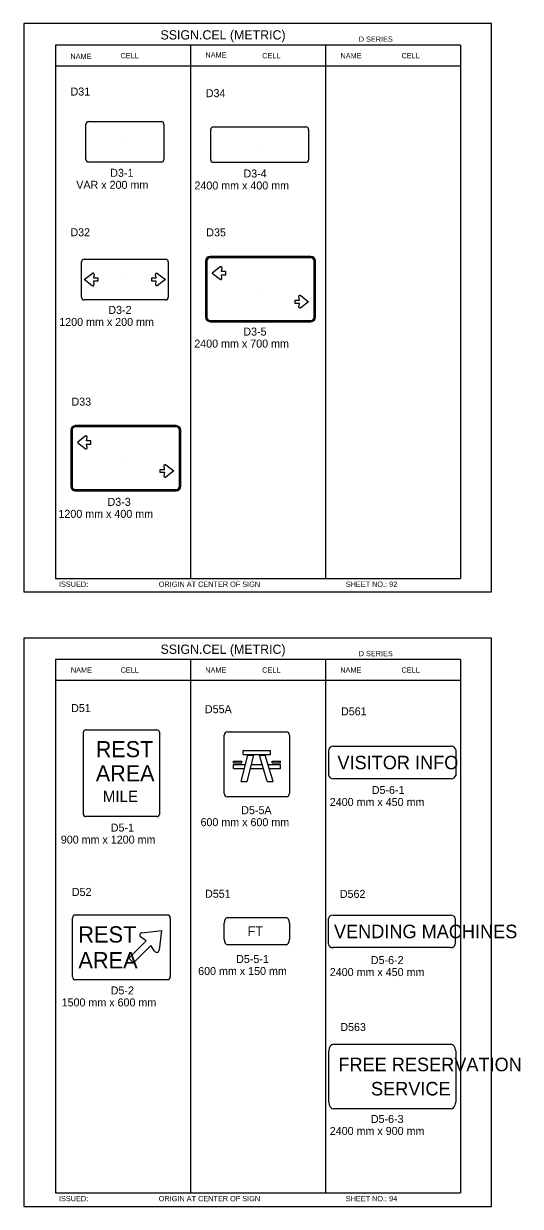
# Model space of a CAD drawing. Extents: x -12 to 6962, y -3756 to 679.
# Drawn here: x 4391.6 to 4577.7, y -235.4 to 208 of the extents above; entities that cross this region are included whole.
import ezdxf

# ---------------------------------------------------------------- set-up
doc = ezdxf.new("R2010")
doc.units = 0
for name, color, linetype in [('Level 1', 7, 'Continuous'), ('Level 2', 7, 'Continuous'), ('Level 3', 7, 'Continuous'), ('Level 61', 7, 'Continuous')]:
    doc.layers.add(name, color=color, linetype=linetype)

msp = doc.modelspace()

# ---------------------------------------------------------------- linework, layer by layer
at = {"layer": 'Level 1'}
for p, q in [((4555.25, 200), (4403.5, 200)), ((4403.5, 200), (4403.5, 0)), ((4454.08, 200), (4454.08, 0)), ((4504.67, 200), (4504.67, 0)), ((4555.25, 200), (4555.25, 0)), ((4555.25, 192.08), (4403.5, 192.08)), ((4414.93, 157.11), (4414.93, 170.35)), ((4415.93, 171.35), (4443.11, 171.35)), ((4444.11, 170.35), (4444.11, 157.11)), ((4462.7, 169.33), (4497.33, 169.33)), ((4461.7, 157), (4461.7, 168.33)), ((4498.33, 168.33), (4498.33, 157)), ((4429.52, 163.73), (4429.52, 163.73)), ((4480.02, 162.66), (4480.02, 162.66)), ((4443.11, 156.11), (4415.93, 156.11)), ((4497.33, 156), (4462.7, 156)), ((4499.24, 120.78), (4461.43, 120.78)), ((4499.24, 120.28), (4461.43, 120.28)), ((4413.27, 105.46), (4413.27, 118.7)), ((4414.27, 119.7), (4444.78, 119.7)), ((4445.78, 118.7), (4445.78, 105.46)), ((4459.73, 119.08), (4459.73, 98)), ((4460.23, 119.08), (4460.23, 98)), ((4500.44, 98), (4500.44, 119.08)), ((4500.94, 98), (4500.94, 119.08)), ((4414.34, 112.09), (4417.28, 114.41)), ((4417.25, 109.8), (4414.34, 112.09)), ((4419.39, 111.47), (4417.74, 111.47)), ((4417.74, 111.47), (4417.96, 110.19)), ((4417.98, 114), (4417.75, 112.7)), ((4417.75, 112.7), (4419.39, 112.7)), ((4419.39, 112.7), (4419.39, 111.47)), ((4429.52, 112.08), (4429.52, 112.08)), ((4480.33, 108.54), (4480.33, 108.54)), ((4444.78, 104.46), (4414.27, 104.46)), ((4461.43, 96.8), (4499.24, 96.8)), ((4461.43, 96.3), (4499.24, 96.3)), ((4409.24, 55.62), (4409.24, 34.54)), ((4409.74, 55.62), (4409.74, 34.54)), ((4448.74, 57.32), (4410.94, 57.32)), ((4448.74, 56.82), (4410.94, 56.82)), ((4449.94, 34.54), (4449.94, 55.62)), ((4450.44, 34.54), (4450.44, 55.62)), ((4429.84, 45.08), (4429.84, 45.08)), ((4410.94, 33.34), (4448.74, 33.34)), ((4410.94, 32.84), (4448.74, 32.84)), ((4403.5, 0), (4555.25, 0)), ((4555.25, -30.35), (4403.5, -30.35)), ((4403.5, -30.35), (4403.5, -230.35)), ((4454.08, -30.35), (4454.08, -230.35)), ((4504.67, -30.35), (4504.67, -230.35)), ((4555.25, -30.35), (4555.25, -230.35)), ((4555.25, -38.27), (4403.5, -38.27)), ((4473.09, -76.1), (4475.6, -66.23)), ((4473.83, -64.47), (4484.09, -64.47)), ((4473.83, -65.92), (4473.83, -64.47)), ((4473.83, -65.92), (4484.09, -65.92)), ((4475.31, -76.1), (4477.83, -66.23)), ((4475.6, -66.23), (4477.83, -66.23)), ((4482.83, -76.1), (4479.9, -66.23)), ((4479.9, -66.23), (4482.12, -66.23)), ((4485.04, -76.1), (4482.12, -66.23)), ((4484.09, -65.92), (4484.09, -64.47)), ((4470.18, -68.51), (4473.33, -68.51)), ((4470.18, -69.07), (4470.18, -68.51)), ((4470.18, -69.07), (4473.33, -69.07)), ((4470.18, -69.68), (4474.72, -69.68)), ((4470.18, -71.18), (4470.18, -69.68)), ((4473.33, -69.07), (4473.33, -68.51)), ((4476.95, -69.68), (4480.93, -69.68)), ((4478.94, -69.68), (4478.94, -69.68)), ((4483.14, -69.68), (4487.83, -69.68)), ((4484.68, -68.51), (4487.83, -68.51)), ((4484.68, -69.07), (4484.68, -68.51)), ((4484.68, -69.07), (4487.83, -69.07)), ((4487.83, -69.07), (4487.83, -68.51)), ((4487.83, -71.18), (4487.83, -69.68)), ((4529.7, -68.98), (4529.7, -68.98)), ((4428.21, -73.02), (4428.21, -73.02)), ((4428.21, -73.02), (4428.21, -73.02)), ((4428.21, -73.02), (4428.21, -73.02)), ((4470.18, -71.18), (4474.34, -71.18)), ((4476.57, -71.18), (4481.37, -71.18)), ((4483.59, -71.18), (4487.83, -71.18)), ((4473.09, -76.1), (4475.31, -76.1)), ((4482.83, -76.1), (4485.04, -76.1)), ((4435.87, -132.83), (4443.23, -131.96)), ((4443.23, -131.96), (4442.36, -139.4)), ((4478.96, -132.23), (4478.96, -132.23)), ((4529.47, -132.33), (4529.47, -132.33)), ((4431.05, -142.39), (4437.55, -135.89)), ((4437.55, -135.89), (4435.42, -134.4)), ((4428.21, -138.28), (4428.21, -138.28)), ((4439.26, -137.65), (4432.79, -144.12)), ((4440.77, -139.81), (4439.26, -137.65)), ((4432.79, -144.12), (4431.05, -142.39)), ((4529.7, -186.74), (4529.7, -186.74)), ((4403.5, -230.35), (4555.25, -230.35))]:
    msp.add_line(p, q, dxfattribs=at)
for points in [[(4462.26, 114.49), (4465.17, 112.2), (4465.25, 112.14), (4465.37, 112.11), (4465.5, 112.11), (4465.61, 112.14), (4465.71, 112.2), (4465.78, 112.26), (4465.84, 112.37), (4465.85, 112.39), (4465.88, 112.48), (4465.88, 112.57), (4465.89, 112.59), (4465.66, 113.87), (4467.31, 113.87), (4467.31, 115.1), (4465.68, 115.1), (4465.91, 116.4), (4465.9, 116.4), (4465.91, 116.47), (4465.88, 116.58), (4465.87, 116.68), (4465.81, 116.76), (4465.73, 116.84), (4465.66, 116.86), (4465.58, 116.89), (4465.51, 116.91), (4465.41, 116.9), (4465.32, 116.87), (4465.2, 116.81), (4462.26, 114.49)], [(4444.7, 112.09), (4441.79, 109.81), (4441.71, 109.75), (4441.59, 109.72), (4441.46, 109.71), (4441.36, 109.75), (4441.25, 109.8), (4441.19, 109.87), (4441.12, 109.97), (4441.11, 109.99), (4441.08, 110.09), (4441.09, 110.17), (4441.08, 110.19), (4441.3, 111.47), (4439.65, 111.47), (4439.65, 112.7), (4441.29, 112.7), (4441.06, 114), (4441.06, 114.01), (4441.06, 114.08), (4441.08, 114.19), (4441.09, 114.29), (4441.16, 114.36), (4441.23, 114.44), (4441.3, 114.47), (4441.38, 114.5), (4441.45, 114.52), (4441.56, 114.51), (4441.65, 114.48), (4441.76, 114.41), (4444.7, 112.09)], [(4498.34, 103.78), (4495.43, 101.5), (4495.35, 101.44), (4495.23, 101.41), (4495.1, 101.4), (4494.99, 101.44), (4494.89, 101.49), (4494.82, 101.55), (4494.76, 101.66), (4494.74, 101.68), (4494.71, 101.77), (4494.72, 101.86), (4494.71, 101.88), (4494.94, 103.16), (4493.28, 103.16), (4493.28, 104.39), (4494.92, 104.39), (4494.69, 105.69), (4494.7, 105.7), (4494.69, 105.76), (4494.71, 105.87), (4494.72, 105.98), (4494.79, 106.05), (4494.87, 106.13), (4494.93, 106.16), (4495.02, 106.19), (4495.09, 106.21), (4495.19, 106.2), (4495.28, 106.17), (4495.4, 106.1), (4498.34, 103.78)], [(4411.77, 51.03), (4414.68, 48.74), (4414.76, 48.68), (4414.88, 48.65), (4415.01, 48.65), (4415.11, 48.68), (4415.22, 48.73), (4415.28, 48.8), (4415.35, 48.91), (4415.36, 48.93), (4415.39, 49.02), (4415.38, 49.11), (4415.39, 49.13), (4415.17, 50.41), (4416.82, 50.41), (4416.82, 51.64), (4415.18, 51.64), (4415.41, 52.93), (4415.41, 52.94), (4415.41, 53.01), (4415.39, 53.12), (4415.38, 53.22), (4415.31, 53.3), (4415.24, 53.38), (4415.17, 53.4), (4415.09, 53.43), (4415.02, 53.45), (4414.91, 53.44), (4414.82, 53.41), (4414.71, 53.35), (4411.77, 51.03)], [(4447.84, 40.32), (4444.93, 38.03), (4444.85, 37.97), (4444.73, 37.94), (4444.6, 37.94), (4444.5, 37.97), (4444.39, 38.02), (4444.33, 38.09), (4444.26, 38.2), (4444.25, 38.22), (4444.22, 38.31), (4444.23, 38.4), (4444.22, 38.42), (4444.44, 39.7), (4442.79, 39.7), (4442.79, 40.93), (4444.43, 40.93), (4444.2, 42.23), (4444.2, 42.23), (4444.2, 42.3), (4444.22, 42.41), (4444.23, 42.51), (4444.3, 42.59), (4444.37, 42.67), (4444.44, 42.69), (4444.52, 42.72), (4444.59, 42.74), (4444.7, 42.73), (4444.79, 42.7), (4444.9, 42.64), (4447.84, 40.32)]]:
    msp.add_lwpolyline(points, dxfattribs=at)
for centre, radius, start, end in [((4415.93, 170.35), 1, 90, 180), ((4443.11, 170.35), 1, 0, 90), ((4462.7, 168.33), 1, 90, 180), ((4497.33, 168.33), 1, 0, 90), ((4415.93, 157.11), 1, 180, 270), ((4443.11, 157.11), 1, 270, 0), ((4462.7, 157), 1, 180, 270), ((4497.33, 157), 1, 270, 0), ((4461.43, 119.08), 1.7, 90, 180), ((4461.43, 119.08), 1.2, 90, 180), ((4499.24, 119.08), 1.7, 0, 90), ((4499.24, 119.08), 1.2, 0, 90), ((4414.27, 118.7), 1, 90, 180), ((4444.78, 118.7), 1, 0, 90), ((4417.55, 114.08), 0.435, 348.2476, 132.1543), ((4417.53, 110.14), 0.435, 229.8591, 10.5247), ((4414.27, 105.46), 1, 180, 270), ((4444.78, 105.46), 1, 270, 0), ((4461.43, 98), 1.7, 180, 270), ((4461.43, 98), 1.2, 180, 270), ((4499.24, 98), 1.2, 270, 0), ((4499.24, 98), 1.7, 270, 0), ((4410.94, 55.62), 1.7, 90, 180), ((4410.94, 55.62), 1.2, 90, 180), ((4448.74, 55.62), 1.7, 0, 90), ((4448.74, 55.62), 1.2, 0, 90), ((4410.94, 34.54), 1.7, 180, 270), ((4410.94, 34.54), 1.2, 180, 270), ((4448.74, 34.54), 1.2, 270, 0), ((4448.74, 34.54), 1.7, 270, 0), ((4435.96, -133.71), 0.869, 94.8591, 235.5247), ((4441.49, -139.31), 0.869, 213.2476, 357.1543)]:
    msp.add_arc(centre, radius, start, end, dxfattribs=at)
at = {"layer": 'Level 3'}
for p, q in [((4413.99, -88.47), (4413.99, -57.58)), ((4414.94, -56.77), (4441.49, -56.77)), ((4442.44, -57.58), (4442.44, -88.47)), ((4467.99, -57.49), (4489.93, -57.49)), ((4466.77, -80.66), (4466.77, -58.71)), ((4491.15, -58.71), (4491.15, -80.66)), ((4505.97, -73.8), (4505.97, -64.17)), ((4505.97, -73.8), (4505.97, -64.17)), ((4507.72, -62.92), (4551.69, -62.92)), ((4507.72, -62.92), (4551.69, -62.92)), ((4507.72, -62.92), (4551.69, -62.92)), ((4507.72, -62.92), (4551.69, -62.92)), ((4553.44, -64.17), (4553.44, -73.8)), ((4553.44, -64.17), (4553.44, -73.8)), ((4551.69, -75.05), (4507.72, -75.05)), ((4551.69, -75.05), (4507.72, -75.05)), ((4489.93, -81.87), (4467.99, -81.87)), ((4441.49, -89.28), (4414.94, -89.28)), ((4409.93, -149.25), (4409.93, -127.31)), ((4410.66, -126.09), (4445.77, -126.09)), ((4446.5, -127.31), (4446.5, -149.25)), ((4467.99, -127.15), (4489.93, -127.15)), ((4505.74, -137.14), (4505.74, -127.51)), ((4507.49, -126.26), (4551.45, -126.26)), ((4553.21, -127.51), (4553.21, -137.14)), ((4466.77, -135.27), (4466.77, -129.18)), ((4491.15, -129.18), (4491.15, -135.27)), ((4489.93, -137.31), (4467.99, -137.31)), ((4551.45, -138.39), (4507.49, -138.39)), ((4445.77, -150.47), (4410.66, -150.47)), ((4505.97, -196.37), (4505.97, -177.11)), ((4507.72, -174.61), (4551.69, -174.61)), ((4553.44, -177.11), (4553.44, -196.37)), ((4551.69, -198.87), (4507.72, -198.87))]:
    msp.add_line(p, q, dxfattribs=at)
for centre, start, end in [((4467.99, -58.71), 90, 180), ((4489.93, -58.71), 0, 90), ((4467.99, -80.66), 180, 270), ((4489.93, -80.66), 270, 0)]:
    msp.add_arc(centre, 1.22, start, end, dxfattribs=at)
for centre, major_axis, ratio, start_param, end_param in [((4414.94, -57.58), (-0.948, 0), 0.857082, 4.712389, 6.283185), ((4441.49, -57.58), (-0.948, 0), 0.857082, 3.141593, 4.712389), ((4507.72, -64.17), (-1.75, 0), 0.714775, 4.712389, 6.283185), ((4507.72, -64.17), (-1.75, 0), 0.714775, 4.712389, 6.283185), ((4551.69, -64.17), (-1.75, 0), 0.714775, 3.141593, 4.712389), ((4551.69, -64.17), (-1.75, 0), 0.714775, 3.141593, 4.712389), ((4507.72, -73.8), (-1.75, 0), 0.714775, 0, 1.570796), ((4507.72, -73.8), (-1.75, 0), 0.714775, 0, 1.570796), ((4551.69, -73.8), (1.75, 0), 0.714775, 4.712389, 6.283185), ((4551.69, -73.8), (1.75, 0), 0.714775, 4.712389, 6.283185), ((4414.94, -88.47), (0.948, 0), 0.857082, 3.141593, 4.712389), ((4441.49, -88.47), (0.948, 0), 0.857082, 4.712389, 6.283185), ((4410.66, -127.31), (0, -1.22), 0.6, 3.141593, 4.712389), ((4445.77, -127.31), (0, 1.22), 0.6, 4.712389, 6.283185), ((4467.99, -129.18), (0, -2.03), 0.6, 3.141593, 4.712389), ((4489.93, -129.18), (0, 2.03), 0.6, 4.712389, 6.283185), ((4507.49, -127.51), (-1.75, 0), 0.714775, 4.712389, 6.283185), ((4551.45, -127.51), (-1.75, 0), 0.714775, 3.141593, 4.712389), ((4467.99, -135.27), (0, -2.03), 0.6, 4.712389, 6.283185), ((4489.93, -135.27), (0, 2.03), 0.6, 3.141593, 4.712389), ((4507.49, -137.14), (-1.75, 0), 0.714775, 0, 1.570796), ((4551.45, -137.14), (1.75, 0), 0.714775, 4.712389, 6.283185), ((4410.66, -149.25), (0, -1.22), 0.6, 4.712389, 6.283185), ((4445.77, -149.25), (0, 1.22), 0.6, 3.141593, 4.712389), ((4507.72, -177.11), (0, 2.51), 0.699521, 0, 1.570796), ((4551.69, -177.11), (0, 2.51), 0.699521, 4.712389, 6.283185), ((4507.72, -196.37), (0, -2.51), 0.699521, 4.712389, 6.283185), ((4551.69, -196.37), (0, -2.51), 0.699521, 0, 1.570796)]:
    msp.add_ellipse(centre, major_axis=major_axis, ratio=ratio, start_param=start_param, end_param=end_param, dxfattribs=at)
at = {"layer": 'Level 61'}
for points in [[(4391.62, -5.05), (4566.88, -5.05), (4566.88, 208.05), (4391.62, 208.05)], [(4391.62, -235.4), (4566.88, -235.4), (4566.88, -22.31), (4391.62, -22.31)]]:
    msp.add_lwpolyline(points, close=True, dxfattribs=at)

# ---------------------------------------------------------------- texts
at = {"layer": 'Level 1'}
for s, height, p in [('REST', 6.035, (4418.63, -66.99)), ('VISITOR INFO', 5.0797, (4509.15, -71.52)), ('AREA', 6.035, (4418.65, -76.04)), ('  MILE', 4.225, (4418.13, -83.8)), ('REST', 6.096, (4412.08, -136.5)), ('     FT', 3.556, (4468.89, -134)), ('VENDING MACHINES', 5.0797, (4507.84, -134.87)), ('AREA', 6.096, (4412.11, -146.15)), ('FREE RESERVATION', 5.0797, (4509.51, -184.74)), ('SERVICE', 5.08, (4521.72, -193.83))]:
    msp.add_text(s, height=height, dxfattribs=at).set_placement(p)
at = {"layer": 'Level 2'}
for s, p in [('D31', (4409.17, 181.09)), ('D34', (4459.83, 180.48)), ('D32', (4409.13, 128.33)), ('D35', (4460.01, 128.29)), ('D33', (4409.52, 64.82)), ('D51', (4409.38, -50.07)), ('D55A', (4459.51, -50.49)), ('D561', (4510.49, -51.3)), ('D52', (4409.67, -119.01)), ('D551', (4459.56, -119.7)), ('D562', (4510.04, -119.75)), ('D563', (4510.23, -169.66))]:
    msp.add_text(s, height=3, dxfattribs=at).set_placement(p)
at = {"layer": 'Level 3'}
for s, height, p in [('SSIGN.CEL (METRIC)', 3.4642, (4442.88, 202.11)), ('D SERIES', 1.979, (4517.13, 201.24)), ('NAME', 1.98, (4409.12, 194.78)), ('CELL', 1.98, (4427.93, 195.04)), ('NAME', 1.98, (4459.69, 195.3)), ('CELL', 1.98, (4480.95, 195.04)), ('NAME', 1.98, (4510.28, 195.04)), ('CELL', 1.98, (4533.15, 195.04)), ('D3-1', 3, (4424.04, 150.62)), ('D3-4', 3, (4473.95, 150.37)), ('VAR x 200 mm', 3, (4411.32, 146.12)), ('2400 mm x 400 mm', 3, (4455.58, 145.87)), ('D3-2', 3, (4423.33, 99.21)), ('1200 mm x 200 mm', 3, (4404.95, 94.71)), ('D3-5', 3, (4473.9, 91.09)), ('2400 mm x 700 mm', 3, (4455.52, 86.59)), ('D3-3', 3, (4423.03, 27.25)), ('1200 mm x 400 mm', 3, (4404.65, 22.75)), ('ISSUED:', 1.98, (4404.84, -3.12)), ('ORIGIN AT CENTER OF SIGN', 1.9795, (4442.22, -3.12)), ('SHEET NO.: 92', 1.9795, (4512.26, -3.12)), ('SSIGN.CEL (METRIC)', 3.4642, (4442.88, -28.24)), ('D SERIES', 1.979, (4517.13, -29.12)), ('NAME', 1.98, (4409.3, -35.31)), ('CELL', 1.98, (4427.93, -35.31)), ('NAME', 1.98, (4459.63, -35.31)), ('CELL', 1.98, (4480.95, -35.31)), ('NAME', 1.98, (4510.23, -35.31)), ('CELL', 1.98, (4533.15, -35.31)), ('D5-6-1', 3, (4522, -80.8)), ('2400 mm x 450 mm', 3, (4506.28, -85.3)), ('D5-5A', 3, (4473.11, -88.36)), ('D5-1', 3, (4424.25, -94.9)), ('600 mm x 600 mm', 3, (4457.86, -92.86)), ('900 mm x 1200 mm', 3, (4405.53, -99.4)), ('D5-5-1', 3, (4471.19, -144.16)), ('D5-6-2', 3, (4521.65, -144.56)), ('600 mm x 150 mm', 3, (4456.97, -148.66)), ('2400 mm x 450 mm', 3, (4506.28, -149.06)), ('D5-2', 3, (4424.21, -155.94)), ('1500 mm x 600 mm', 3, (4405.83, -160.44)), ('D5-6-3', 3, (4521.65, -204.14)), ('2400 mm x 900 mm', 3, (4506.28, -208.64)), ('ISSUED:', 1.98, (4404.84, -233.48)), ('ORIGIN AT CENTER OF SIGN', 1.9795, (4442.22, -233.48)), ('SHEET NO.: 94', 1.9795, (4512.26, -233.48))]:
    msp.add_text(s, height=height, dxfattribs=at).set_placement(p)

doc.saveas('drawing.dxf')
